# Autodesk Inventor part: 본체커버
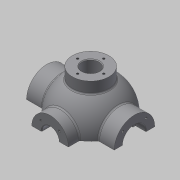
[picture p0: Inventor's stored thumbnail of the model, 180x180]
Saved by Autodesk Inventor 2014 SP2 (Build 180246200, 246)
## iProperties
Created: 2015-12
Part Number: 본체커버
Material: 일반
Document SubType Name: Modeling
Designer: mduedu
Density: 1 g/cm^3
Mass: 211.839 g
Surface Area: 451.737 cm^2
Volume: 211.839 cm^3
Appearance: 기본값
Author: mduedu
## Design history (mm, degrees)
sketch "스케치1"
  geometry: L1 (-53, 0)-(53, 0); A1 r 53 centre (0, 0) between (53, 0) and (-53, 0); 2 further points
  constraints: 2 coincident, 2 end point, 2 point on circle, 1 centre point, 1 horizontal, 1 midpoint
  dimensions: "d0" = 53 radius of A1
revolve "회전1" sketch "스케치1" stored, may be unused: angle "d2" = 90 deg
feature "쉘1" dims "d11" = 10
node "작업 평면1"
sketch "스케치2"
  geometry: C1 r 31 at (0, 0); 1 further point
  constraints: 1 centre point, 1 coincident
  dimensions: "d4" = 62 diameter of C1
extrude "돌출1" join sketch "스케치2" stored distance "d5" = 10; taper "d6" = 0 deg
node "작업 평면2"
sketch "스케치3"
  geometry: C1 r 28 at (0, 0); 1 further point
  constraints: 1 centre point, 1 coincident
  dimensions: "d8" = 56 diameter of C1
extrude "돌출2" join sketch "스케치3" stored distance "d9" = 10; taper "d10" = 0 deg
hole "구멍1" diameter "d14" = 35; stored, may be unused: countersink angle "d18" = 90 deg, drill point angle "d20" = 0 deg; dims "d12" = 10, "d13" = 10, "d15" = 6, "d16" = 4, "d17" = 2, "d19" = 16
hole "구멍2" diameter "d23" = 27; stored, may be unused: countersink angle "d27" = 90 deg, drill point angle "d29" = 0 deg; dims "d21" = 10, "d22" = 10, "d24" = 6, "d25" = 4, "d26" = 2, "d28" = 16
fillet "모깎기1" dims "d30" = 0.3
hole "구멍3" diameter "d33" = 26; stored, may be unused: countersink angle "d37" = 90 deg, drill point angle "d39" = 0 deg; dims "d31" = 10, "d32" = 10, "d34" = 6, "d35" = 4, "d36" = 2, "d38" = 16
chamfer "모따기1" distance "d40" = 1; stored, may be unused: second distance "d41" = 2, angle "d42" = 45 deg
sketch "스케치4"
  geometry: L1 (0, 0)-(0, -25); L2 (0, 0)-(-17.678, -17.678); A1 r 25 centre (0, 0) between (-17.678, -17.678) and (0, -25); 1 further point
  constraints: 4 end point, 2 point on circle, 1 centre point, 1 coincident, 1 vertical
  dimensions: "d43" = 50 diameter of A1; "d47" = 45 deg angle of L1 L2
hole "구멍4" sketch "스케치4" at (-17.678, -17.678) diameter "d49" = 3.242; stored, may be unused: countersink angle "d53" = 90 deg, drill point angle "d55" = 118 deg; dims "d50" = 11, "d51" = 4, "d52" = 2, "d54" = 13
sketch "스케치5"
  geometry: L1 (0, 0)-(0, -20); L2 (0, 0)-(-14.142, -14.142); A1 r 20 centre (0, 0) between (0, -20) and (-14.142, -14.142); 2 further points
  constraints: 4 end point, 2 coincident, 2 point on circle, 1 centre point, 1 vertical
  dimensions: "d59" = 40 diameter of A1; "d65" = 45 deg angle of L1 L2
hole "구멍5" sketch "스케치5" at (-14.142, -14.142) diameter "d67" = 3.242; stored, may be unused: countersink angle "d71" = 90 deg, drill point angle "d73" = 118 deg; dims "d68" = 8, "d69" = 4, "d70" = 2, "d72" = 10
node "작업 평면3"
sketch "스케치6"
  geometry: C1 r 65 at (0, 0); 1 further point
  constraints: 1 centre point, 1 coincident
  dimensions: "d78" = 130 diameter of C1
extrude "돌출3" join sketch "스케치6" distance "d80" = 10; taper "d81" = 0 deg
sketch "스케치7"
  geometry: C1 r 20 at (0, 0); 1 further point
  constraints: 1 centre point, 1 coincident
  dimensions: "d82" = 40 diameter of C1
extrude "돌출4" join sketch "스케치7" stored distance "d84" = 10; taper "d85" = 0 deg
sketch "스케치8"
  geometry: 2 further points
  constraints: 1 coincident
hole "구멍6" sketch "스케치8" at (0, 0) diameter "d86" = 20; stored, may be unused: countersink angle "d90" = 90 deg, drill point angle "d92" = 118 deg; dims "d87" = 7, "d88" = 40, "d89" = 5, "d91" = 10
fillet "모깎기2" dims "d93" = 0.3
sketch "스케치9"
  geometry: L1 (65, -75)-(-65, -75) reference; L2 (-45, -75)-(-38.245, -36.692); A1 r 53 centre (0, 0) between (42.988, 31) and (42.988, -31) reference; 1 further point
  constraints: 2 end point, 1 point on circle, 1 point on line
  dimensions: "d94" = 45 horizontal distance of L2.start point (0, 0); "d95" = 80 deg angle of L2 L1
feature "리브1" sketch "스케치9" dims "d96" = 1, "d97" = 8, "d98" = 0, "d99" = 0, "d100" = 1, "d101" = 1
sketch "스케치10"
  geometry: L1 (0, 0)-(0, -55); L2 (0, 0)-(-38.891, -38.891); A1 r 55 centre (0, 0) between (0, -55) and (-38.891, -38.891); 2 further points
  constraints: 4 end point, 2 coincident, 2 point on circle, 1 centre point, 1 vertical
  dimensions: "d105" = 110 diameter of A1; "d107" = 45 deg angle of L1 L2
hole "구멍7" sketch "스케치10" at (-38.891, -38.891) diameter "d109" = 10; stored, may be unused: countersink angle "d113" = 90 deg, drill point angle "d115" = 118 deg; dims "d110" = 7, "d111" = 40, "d112" = 5, "d114" = 10
fillet "모깎기3" dims "d120" = 3
fillet "모깎기4" dims "d121" = 3, "d122" = 3
fillet "모깎기5" dims "d123" = 3
fillet "모깎기6" dims "d124" = 3
sketch "스케치11"
  geometry: C1 r 5 at (-38.891, 38.891) reference; C2 r 5 at (38.891, 38.891) reference; C3 r 5 at (38.891, -38.891) reference; C4 r 5 at (-38.891, -38.891) reference; C5 r 20 at (0, 0) reference; C6 r 65 at (0, 0) reference; 1 further point
  constraints: 3 other
feature "엠보싱1" sketch "스케치11" dims "d125" = 0.5, "d126" = 0
sketch "스케치12"
  geometry: L1 (0, 100)-(0, -100); L2 (0, 100)-(-150, 100); L3 (-150, 100)-(-150, -100); L4 (-150, -100)-(0, -100); 2 further points
  constraints: 8 end point, 3 perpendicular, 1 coincident, 1 midpoint, 1 vertical
  dimensions: "d127" = 200 distance of L2.end L3.end; "d129" = 150 distance of L3.end L1.end
extrude "돌출5" cut sketch "스케치12" stored distance "d130" = 10; taper "d131" = 0 deg
sketch "스케치13"
  geometry: C1 r 7 at (0, -53); A1 r 53 centre (0, 0) between (-42.113, -32.179) and (42.113, -32.179) reference; 1 further point
  constraints: 1 centre point, 1 point on circle
  dimensions: "d132" = 14 diameter of C1
extrude "돌출6" join sketch "스케치13" distance "d133" = 5; taper "d134" = 0 deg
sketch "스케치14"
  geometry: C1 r 7 at (0, 0) reference; 1 further point
extrude "돌출7" cut sketch "스케치14" stored distance "d135" = 5; taper "d136" = 0 deg
sketch "스케치15"
  geometry: C1 r 2.25 at (0, 53); A1 r 7 centre (0, 53) between (6.965, 52.302) and (-6.965, 52.302) reference; 1 further point
  constraints: 1 centre point, 1 coincident
  dimensions: "d139" = 4.5 diameter of C1
extrude "돌출8" cut sketch "스케치15" stored distance "d141" = 5; taper "d142" = 0 deg
fillet "모깎기7" dims "d143" = 3
fillet "모깎기8" dims "d144" = 1
fillet "모깎기9" dims "d145" = 1
fillet "모깎기10" dims "d146" = 1
node "작업 평면4"
sketch "스케치16"
  geometry: C1 r 28 at (0, 0); 1 further point
  constraints: 1 centre point, 1 coincident
  dimensions: "d148" = 56 diameter of C1
extrude "돌출9" join sketch "스케치16" stored distance "d150" = 5; taper "d151" = 0 deg
hole "구멍8" diameter "d154" = 26; stored, may be unused: countersink angle "d158" = 90 deg, drill point angle "d160" = 118 deg; dims "d152" = 10, "d153" = 10, "d155" = 6, "d156" = 4, "d157" = 2, "d159" = 8
sketch "스케치17" dims "d161" = 40
  geometry: 3 further points
  constraints: 2 vertical alignment, 1 coincident, 2 other
hole "구멍9" sketch "스케치17" at (0, 20) diameter "d163" = 3.242; stored, may be unused: countersink angle "d167" = 90 deg, drill point angle "d169" = 118 deg; dims "d164" = 8, "d165" = 4, "d166" = 2, "d168" = 10
fillet "모깎기11" dims "d173" = 3
chamfer "모따기2" distance "d174" = 1; stored, may be unused: second distance "d175" = 2, angle "d176" = 45 deg
node "솔리드1"
mirror "대칭1"
mirror "대칭2"
pattern_circular "원형 패턴1" dims angle "d57" = 360 deg
mirror "대칭3"
pattern_circular "원형 패턴2" dims angle "d75" = 360 deg
pattern_circular "원형 패턴3" dims angle "d103" = 360 deg
pattern_circular "원형 패턴4" dims angle "d118" = 360 deg
pattern_circular "원형 패턴5" dims angle "d171" = 360 deg
node "투영된 루프1"
other parameters: "d3" = 67, "d7" = 62, "d77" = -85, "d147" = 62
